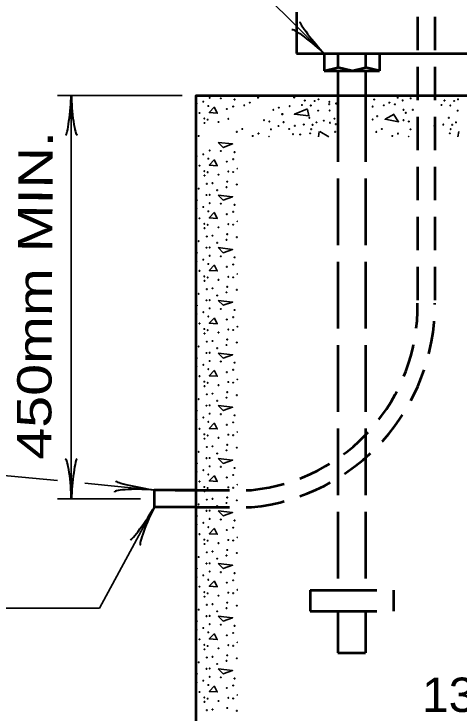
# Model space of a CAD drawing. Extents: x -39 to 816, y -16 to 528.
# Drawn here: x 233.6 to 272.5, y 202.8 to 263.8 of the extents above; entities that cross this region are included whole.
import ezdxf

# ---------------------------------------------------------------- set-up
doc = ezdxf.new("R2010")
doc.units = 0
doc.header["$LTSCALE"] = 0.97
doc.linetypes.add('LONG_DASHED', pattern=[7.5, 6, -1.5])
doc.linetypes.add('MEDIUM_DASHED', pattern=[4.5, 3, -1.5])
doc.layers.add('1', color=7, linetype='Continuous', lineweight=35)

msp = doc.modelspace()

# ---------------------------------------------------------------- linework, layer by layer
at = {"layer": '1'}
for p, q in [((260.7254, 260.3476), (249.2718, 271.7584)), ((248.3174, 256.6996), (237.4454, 256.6996)), ((238.6454, 256.6996), (238.6454, 221.4676)), ((256.7414, 256.6756), (256.7174, 256.6996)), ((268.9334, 256.6756), (268.9094, 256.6996)), ((260.2214, 253.0756), (260.2934, 253.5556)), ((260.3414, 253.5316), (261.1334, 253.0756)), ((272.4134, 253.0756), (272.4854, 253.5556)), ((237.4509, 223.0514), (216.4342, 225.0824)), ((245.8934, 222.2356), (239.8398, 222.8206)), ((237.4454, 221.4676), (244.6934, 221.4676))]:
    msp.add_line(p, q, dxfattribs=at)
at = {"layer": '1', "linetype": 'MEDIUM_DASHED', "lineweight": 53}
for p, q in [((268.8854, 267.9076), (268.8854, 238.5556)), ((270.3974, 267.9076), (270.3974, 238.5556)), ((249.5414, 220.7236), (254.3654, 220.7236))]:
    msp.add_line(p, q, dxfattribs=at)
at = {"layer": '1', "lineweight": 53}
for p, q in [((258.3014, 263.9716), (258.3014, 260.3476)), ((258.3014, 260.3476), (285.5174, 260.3476)), ((260.7254, 260.3476), (260.7254, 258.8356)), ((261.9254, 260.3476), (261.9254, 259.1236)), ((264.3494, 260.3476), (264.3494, 259.1236)), ((265.5494, 260.3476), (265.5494, 258.8356)), ((260.7254, 258.8356), (261.9254, 259.1236)), ((260.7254, 258.8356), (265.5494, 258.8356)), ((263.1494, 258.8356), (261.9254, 259.1236)), ((261.9254, 258.8356), (261.9254, 256.6996)), ((263.1494, 258.8356), (264.3494, 259.1236)), ((265.5494, 258.8356), (264.3494, 259.1236)), ((264.3494, 258.8356), (264.3494, 256.6996)), ((249.5414, 222.2356), (245.8934, 222.2356)), ((245.8934, 222.2356), (245.8934, 220.7236)), ((249.5414, 220.7236), (245.8934, 220.7236))]:
    msp.add_line(p, q, dxfattribs=at)
at = {"layer": '1', "linetype": 'LONG_DASHED', "lineweight": 53}
for p, q in [((261.9254, 256.6996), (261.9254, 213.4756)), ((264.3494, 256.6996), (264.3494, 213.4756)), ((259.5014, 213.4756), (266.7734, 213.4756)), ((259.5014, 213.4756), (259.5014, 211.6516)), ((266.7734, 213.4756), (266.7734, 211.6516)), ((259.5014, 211.6516), (266.7734, 211.6516)), ((261.9254, 211.6516), (261.9254, 208.0276)), ((264.3494, 211.6516), (264.3494, 208.0276)), ((261.9254, 208.0276), (264.3494, 208.0276))]:
    msp.add_line(p, q, dxfattribs=at)
at = {"layer": '1', "lineweight": 53}
msp.add_lwpolyline([(249.5414, 182.9236), (249.5414, 256.6996), (294.2774, 256.6996), (294.2774, 179.2996)], dxfattribs=at)
at = {"layer": '1'}
for points in [[(251.1494, 255.6916), (250.6934, 255.1876), (251.3894, 255.1396), (251.1494, 255.6436)], [(259.2854, 255.5236), (258.1334, 255.0436), (259.4054, 254.8996), (259.2854, 255.4756)], [(266.8454, 255.0436), (266.0534, 254.6116), (267.2294, 254.3956), (266.7974, 255.0676)], [(251.1494, 251.0836), (250.6934, 250.6036), (251.3894, 250.5556), (251.1494, 251.0356)], [(251.1494, 246.4996), (250.6934, 245.9956), (251.3894, 245.9476), (251.1494, 246.4516)], [(251.1494, 241.8916), (250.6934, 241.4116), (251.3894, 241.3636), (251.1494, 241.8436)], [(251.1494, 237.2836), (250.6934, 236.8036), (251.3894, 236.7556), (251.1494, 237.2356)], [(251.1494, 232.6996), (250.6934, 232.2196), (251.3894, 232.1716), (251.1494, 232.6516)], [(251.1494, 228.0916), (250.6934, 227.6116), (251.3894, 227.5636), (251.1494, 228.0436)], [(251.1494, 223.5076), (250.6934, 223.0276), (251.3894, 222.9796), (251.1494, 223.4596)], [(245.8934, 220.7236), (241.0934, 211.9156), (226.1338, 211.9156)], [(251.1494, 218.8996), (250.6934, 218.4196), (251.3894, 218.3716), (251.1494, 218.8516)], [(251.1494, 214.3156), (250.6934, 213.8356), (251.3894, 213.7876), (251.1494, 214.2676)], [(251.1494, 209.7076), (250.6934, 209.2276), (251.3894, 209.1796), (251.1494, 209.6596)], [(251.1494, 205.1236), (250.6934, 204.6436), (251.3894, 204.5956), (251.1494, 205.0756)]]:
    msp.add_lwpolyline(points, dxfattribs=at)
for points in [[(251.4854, 252.5956), (252.7334, 252.4516), (251.9174, 252.1396)], [(251.4854, 247.9876), (252.7334, 247.8436), (251.9174, 247.5556)], [(251.4854, 243.4036), (252.7334, 243.2356), (251.9174, 242.9476)], [(251.4854, 238.7956), (252.7334, 238.6516), (251.9174, 238.3636)], [(251.4854, 234.1876), (252.7334, 234.0436), (251.9174, 233.7556)], [(251.4854, 229.6036), (252.7334, 229.4596), (251.9174, 229.1716)], [(251.4854, 224.9956), (252.7334, 224.8516), (251.9174, 224.5636)], [(251.4854, 220.4116), (252.7334, 220.2676), (251.9174, 219.9796)], [(251.4854, 215.8036), (252.7334, 215.6596), (251.9174, 215.3716)], [(251.4854, 211.2196), (252.7334, 211.0756), (251.9174, 210.7876)], [(251.4854, 206.6116), (252.7334, 206.4676), (251.9174, 206.1796)]]:
    msp.add_lwpolyline(points, close=True, dxfattribs=at)
at = {"layer": '1', "linetype": 'MEDIUM_DASHED', "lineweight": 53}
msp.add_lwpolyline([(247.7174, 222.2356), (249.5414, 222.2356), (254.3654, 222.2356)], dxfattribs=at)
at = {"layer": '1'}
for centre in [(250.7258, 256.4824), (251.7037, 256.4343), (254.958, 256.4984), (258.1161, 256.5145), (267.1507, 256.4984), (268.2889, 256.4343), (249.5783, 255.9911), (250.1715, 256.1456), (250.6136, 255.7666), (252.906, 256.3381), (253.7557, 255.8308), (254.2366, 256.0655), (257.7153, 255.7506), (258.7893, 255.8629), (259.0459, 256.2419), (259.5588, 255.8147), (259.8955, 256.2098), (260.2322, 256.354), (261.162, 255.927), (261.178, 256.1296), (261.7711, 255.9911), (265.0988, 256.3381), (265.9484, 255.8308), (266.4293, 256.0655), (266.9102, 255.9109), (267.5836, 256.2578), (270.9821, 255.8629), (271.2387, 256.2419), (271.7516, 255.8147), (272.0883, 256.2098), (272.4249, 256.354), (249.8349, 255.1573), (252.2327, 255.5101), (252.7778, 255.7185), (256.2885, 255.4299), (256.7695, 255.6224), (260.2001, 255.3657), (261.21, 255.3818), (264.9706, 255.7185), (267.6637, 255.4299), (267.8561, 255.1733), (268.4813, 255.4299), (272.3928, 255.3657), (250.2677, 254.6762), (250.5495, 254.58), (252.3609, 254.6441), (255.471, 254.5318), (257.042, 255.0611), (257.1061, 255.0611), (259.4306, 254.7403), (261.6268, 254.6602), (264.9706, 254.596), (265.3553, 254.8847), (267.6638, 254.5318), (271.6234, 254.7403), (250.2837, 254.2913), (251.4952, 254.3715), (255.9358, 254.4197), (256.7374, 254.0187), (257.1863, 254.3554), (258.1642, 254.0348), (258.9497, 254.147), (259.7191, 254.131), (260.0558, 254.3394), (260.697, 254.4838), (261.2421, 254.3074), (261.7551, 254.179), (268.1286, 254.4197), (270.3569, 254.0348), (271.1425, 254.147), (271.9119, 254.131), (272.2485, 254.3394), (253.0984, 253.5056), (253.5793, 253.7622), (254.99, 253.3612), (256.0801, 253.73), (257.6672, 253.7622), (258.0038, 253.3132), (259.5108, 253.3773), (259.5909, 253.7461), (261.6909, 253.5056), (265.2911, 253.5056), (265.772, 253.7622), (267.1827, 253.3612), (268.2729, 253.73), (271.7035, 253.3773), (271.7837, 253.7461), (249.7708, 253.1527), (254.493, 253.1527), (258.629, 253.2811), (266.6858, 253.1527), (250.1715, 251.5492), (250.7258, 251.8859), (251.7037, 251.8378), (252.906, 251.7416), (249.5783, 251.3946), (250.6136, 251.1702), (252.2327, 250.9136), (252.7778, 251.122), (249.8349, 250.5608), (250.2677, 250.0797), (250.2837, 249.6948), (250.5495, 249.9835), (251.4952, 249.775), (252.3609, 250.0476), (252.7778, 249.9996), (250.9822, 249.0373), (252.2647, 249.1657), (249.7708, 248.5562), (250.4761, 248.9732), (252.2007, 248.6846), (253.0984, 248.9091), (250.4522, 247.9923), (250.7258, 248.0111), (251.3831, 248.412), (249.6104, 247.546), (250.7258, 247.2894), (251.7037, 247.2414), (249.5783, 246.7981), (250.1715, 246.9527), (252.906, 247.1451), (250.6136, 246.5737), (252.2327, 246.3171), (252.7778, 246.5255), (249.8349, 245.9644), (250.2677, 245.4832), (250.5495, 245.387), (252.3609, 245.4511), (252.7778, 245.4031), (250.2837, 245.0984), (251.4952, 245.1785), (250.4761, 244.3768), (250.9822, 244.4409), (252.2647, 244.5692), (253.0984, 244.3126), (249.7708, 243.9598), (251.3831, 243.8155), (252.2007, 244.0881), (249.6104, 242.9495), (250.4522, 243.3958), (250.7258, 243.4146), (250.1715, 242.3562), (250.7258, 242.6929), (251.7037, 242.6449), (252.906, 242.5487), (249.5783, 242.2017), (250.6136, 241.9772), (252.2327, 241.7207), (252.7778, 241.929), (249.8349, 241.3679), (250.2677, 240.8868), (250.2837, 240.5019), (250.5495, 240.7905), (251.4952, 240.5821), (252.3609, 240.8547), (252.7778, 240.8066), (252.2647, 239.9727), (249.7708, 239.3633), (250.4761, 239.7803), (250.9822, 239.8444), (252.2007, 239.4916), (253.0984, 239.7162), (250.4522, 238.7994), (250.7258, 238.8182), (251.3831, 239.219), (249.6104, 238.353), (250.7258, 238.0965), (251.7037, 238.0484), (249.5783, 237.6052), (250.1715, 237.7597), (252.906, 237.9522), (250.6136, 237.3807), (252.2327, 237.1242), (252.7778, 237.3326), (249.8349, 236.7714), (250.2677, 236.2903), (252.3609, 236.2582), (250.2837, 235.9054), (250.5495, 236.1941), (251.4952, 235.9856), (252.7778, 236.2101), (250.4761, 235.1838), (250.9822, 235.2479), (252.2647, 235.3762), (253.0984, 235.1197), (249.7708, 234.7668), (251.3831, 234.6225), (252.2007, 234.8951), (250.4522, 234.2029), (250.7258, 234.2217), (249.6104, 233.7565), (250.1715, 233.1632), (250.7258, 233.5), (251.7037, 233.4519), (252.906, 233.3557), (249.5783, 233.0087), (250.6136, 232.7842), (252.7778, 232.7361), (249.8349, 232.1749), (252.2327, 232.5277), (250.2677, 231.6938), (250.5495, 231.5976), (251.4952, 231.3891), (252.3609, 231.6617), (252.7778, 231.6136), (250.2837, 231.3089), (252.2647, 230.7798), (249.7708, 230.1703), (250.4761, 230.5873), (250.9822, 230.6514), (252.2007, 230.2987), (253.0984, 230.5232), (250.4522, 229.6064), (250.7258, 229.6252), (251.3831, 230.026), (249.6104, 229.16), (250.7258, 228.9035), (249.5783, 228.4122), (250.1715, 228.5668), (251.7037, 228.8554), (252.906, 228.7592), (250.6136, 228.1878), (252.2327, 227.9312), (252.7778, 228.1396), (249.8349, 227.5784), (250.2677, 227.0973), (252.3609, 227.0652), (250.2837, 226.7124), (250.5495, 227.0011), (251.4952, 226.7926), (252.7778, 227.0172), (250.4761, 225.9908), (250.9822, 226.0549), (252.2647, 226.1833), (253.0984, 225.9267), (249.7708, 225.5738), (251.3831, 225.4296), (252.2007, 225.7022), (250.4522, 225.0099), (250.7258, 225.0287), (249.6104, 224.5636), (250.7258, 224.307), (251.7037, 224.259), (252.906, 224.1627), (249.5783, 223.8157), (250.1715, 223.9703), (250.6136, 223.5913), (252.7778, 223.5431), (249.8349, 222.982), (252.2327, 223.3347), (250.2677, 222.5008), (250.5495, 222.4046), (251.4952, 222.1961), (252.3609, 222.4687), (252.7778, 222.4207), (250.2837, 222.116), (252.2647, 221.5868), (249.7708, 220.9774), (250.4761, 221.3944), (250.9822, 221.4585), (252.2007, 221.1057), (253.0984, 221.3302), (250.4522, 220.4134), (250.7258, 220.4322), (251.3831, 220.8331), (249.6104, 219.9671), (249.5783, 219.2193), (250.1715, 219.3738), (250.7258, 219.7105), (251.7037, 219.6625), (252.906, 219.5663), (250.6136, 218.9948), (252.2327, 218.7383), (252.7778, 218.9466), (249.8349, 218.3855), (250.2677, 217.9044), (250.2837, 217.5195), (250.5495, 217.8081), (251.4952, 217.5997), (252.3609, 217.8723), (252.7778, 217.8242), (250.4761, 216.7979), (250.9822, 216.862), (252.2647, 216.9903), (253.0984, 216.7338), (249.7708, 216.3809), (251.3831, 216.2366), (252.2007, 216.5092), (250.4522, 215.817), (250.7258, 215.8358), (249.6104, 215.3706), (250.7258, 215.1141), (251.7037, 215.066), (252.906, 214.9698), (249.5783, 214.6228), (250.1715, 214.7773), (250.6136, 214.3983), (252.7778, 214.3502), (249.8349, 213.789), (252.2327, 214.1418), (250.2677, 213.3079), (250.5495, 213.2117), (252.3609, 213.2758), (252.7778, 213.2277), (250.2837, 212.923), (251.4952, 213.0032), (250.4761, 212.2014), (250.9822, 212.2655), (252.2007, 211.9127), (252.2647, 212.3938), (253.0984, 212.1373), (249.7708, 211.7844), (250.4522, 211.2205), (250.7258, 211.2393), (251.3831, 211.6401), (249.6104, 210.7741), (249.5783, 210.0263), (250.1715, 210.1808), (250.7258, 210.5176), (251.7037, 210.4695), (252.906, 210.3733), (250.6136, 209.8018), (252.2327, 209.5453), (252.7778, 209.7537), (249.8349, 209.1925), (250.2677, 208.7114), (250.2837, 208.3265), (250.5495, 208.6152), (251.4952, 208.4067), (252.3609, 208.6793), (252.7778, 208.6312), (250.4761, 207.6049), (250.9822, 207.669), (252.2647, 207.7974), (253.0984, 207.5408), (249.7708, 207.1879), (251.3831, 207.0436), (252.2007, 207.3163), (250.4522, 206.624), (250.7258, 206.6428), (249.6104, 206.1776), (250.7258, 205.9211), (251.7037, 205.873), (252.906, 205.7768), (249.5783, 205.4298), (250.1715, 205.5844), (250.6136, 205.2054), (252.7778, 205.1572), (249.8349, 204.596), (252.2327, 204.9488), (250.2677, 204.1149), (250.5495, 204.0187), (252.3609, 204.0828), (252.7778, 204.0348), (250.2837, 203.73), (251.4952, 203.8102), (250.4761, 203.0084), (250.9822, 203.0725), (252.2647, 203.2009), (253.0984, 202.9443)]:
    msp.add_circle(centre, 0.032, dxfattribs=at)
for centre, start, end in [((249.6104, 256.7389), 256.94318, 283.05682), ((261.5307, 256.7389), 256.94318, 283.05682), ((261.8032, 256.7389), 256.94318, 283.05682), ((249.5624, 254.179), 207.55181, 152.44819), ((255.9198, 253.0726), 11.5283, 168.4717), ((268.1125, 253.0726), 11.5283, 168.4717), ((253.1625, 250.2882), 89.45269, 270.54731), ((249.5624, 249.5826), 207.55181, 152.44819), ((253.1625, 245.6917), 89.45269, 270.54731), ((249.5624, 244.9861), 207.55181, 152.44819), ((253.1625, 241.0953), 89.45269, 270.54731), ((249.5624, 240.3896), 207.55181, 152.44819), ((253.1625, 236.4988), 89.45269, 270.54731), ((249.5624, 235.7931), 207.55181, 152.44819), ((253.1625, 231.9023), 89.45269, 270.54731), ((249.5624, 231.1966), 207.55181, 152.44819), ((253.1625, 227.3058), 89.45269, 270.54731), ((249.5624, 226.6002), 207.55181, 152.44819), ((253.1625, 222.7093), 89.45269, 270.54731), ((249.5624, 222.0037), 207.55181, 152.44819), ((253.1625, 218.1129), 89.45269, 270.54731), ((249.5624, 217.4072), 207.55181, 152.44819), ((253.1625, 213.5164), 89.45269, 270.54731), ((249.5624, 212.8107), 207.55181, 152.44819), ((253.1625, 208.9199), 89.45269, 270.54731), ((249.5624, 208.2142), 207.55181, 152.44819), ((253.1625, 204.3234), 89.45269, 270.54731), ((249.5624, 203.6178), 207.55181, 152.44819)]:
    msp.add_arc(centre, 0.032, start, end, dxfattribs=at)
at = {"layer": '1', "linetype": 'MEDIUM_DASHED', "lineweight": 53}
for centre, radius, start, end in [((252.5971, 238.4364), 17.8029, 275.72296, 0.41001), ((252.7916, 238.2553), 16.0989, 275.63509, 1.09783)]:
    msp.add_arc(centre, radius, start, end, dxfattribs=at)
at = {"layer": '1', "lineweight": 40}
for centre, major_axis, ratio, start_param, end_param in [((259.9521, 261.4765), (1.3444, -1.6369), 0.07063, 3.1407148, 5.41811), ((259.5637, 261.0369), (1.6503, -1.3796), 0.122415, 0.8963533, 3.1415927), ((238.3916, 255.3524), (0.2125, 2.1246), 0.07063, 3.1407148, 5.41811), ((238.3916, 255.3524), (0.2125, 2.1246), 0.07063, 3.1407148, 5.41811), ((238.9818, 255.3878), (-0.1889, 2.16), 0.122415, 0.8963533, 3.1415927), ((238.9818, 255.3878), (-0.1889, 2.16), 0.122415, 0.8963533, 3.1415927), ((238.3134, 222.7981), (0.1889, -2.16), 0.122415, 0.8963533, 3.1415927), ((238.9035, 222.8335), (-0.2125, -2.1246), 0.07063, 3.1407148, 5.41811), ((244.5795, 222.6177), (2.0777, -0.4125), 0.07063, 3.1407148, 5.41811), ((244.5581, 222.0315), (2.1509, -0.0196), 0.122415, 0.8963533, 3.1415927), ((245.0306, 219.6555), (-1.2053, -1.7625), 0.07063, 6.2823074, 8.5597026), ((245.5655, 219.4036), (0.8701, 1.986), 0.122415, 0.8963533, 3.1415927)]:
    msp.add_ellipse(centre, major_axis=major_axis, ratio=ratio, start_param=start_param, end_param=end_param, dxfattribs=at)

# ---------------------------------------------------------------- texts
at = {"layer": '1', "width": 1.25}
msp.add_text('450mm MIN.', height=3, rotation=89.687, dxfattribs=at).set_placement((236.883, 224.8728))
at = {"layer": '1', "width": 1.05}
msp.add_text('13mm', height=3, dxfattribs=at).set_placement((269.2658, 202.8533))

doc.saveas('drawing.dxf')
